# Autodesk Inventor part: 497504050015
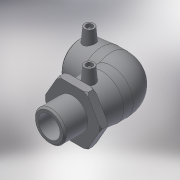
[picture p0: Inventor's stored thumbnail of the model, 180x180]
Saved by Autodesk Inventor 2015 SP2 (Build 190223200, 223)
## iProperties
Created: 2017-06
Part Number: 497504050015
Material: Generic
Description: PE Male Transition Elbow 90° 50x  1 1_2
Document SubType Name: Modeling
Designer: KIM
Mass: 410.436 g
Surface Area: 782.308 cm^2
Volume: 410.436 cm^3
Density: 1 g/cm^3
Appearance: Default
Author: KIM
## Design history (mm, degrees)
derived "497504.ipt"
feature "Solid1::497504.ipt"
feature "Solid2::497504.ipt"
tag "TaggingFeature1"
workplane "Work Plane2"
body "Solid1"
body "Solid2"
other parameters: "d2" = 68, "d4" = 33.33333, "d5" = 61.2, "d8" = 168 deg, "d10" = 19.2, "d11" = 6.4, "d29" = 52, "d30" = 15, "d31" = 52, "d34" = 5 deg, "d41" = 4, "d42" = 14, "d43" = 0, "d48" = 66, "d50" = 5, "d51" = 19.2, "d52" = 48, "d54" = 90 deg, "d86" = 3, "d87" = 0, "d93" = 0.1, "d94" = 12, "d95" = 47.803, "d96" = 33.4621, "d97" = 38, "d98" = 48, "d99" = 88.4, "d100" = 43.2, "d102" = 2.5, "d106" = 0, "d108" = 38.4, "d114" = 48, "d115" = 0, "d116" = -48, "L_" = 148, "L_1" = 48, "D_" = 38, "A_" = 52, "d_2" = 12, "L_2" = 48, "D_1" = 68, "R_" = 47.803
